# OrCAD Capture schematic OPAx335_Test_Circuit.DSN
size A; title: 0.05µV/°C max, SINGLE-SUPPLY CMOS OPERATIONAL; rev: 1.5; note: Datasheet: SBOS245D  EVM: N/A
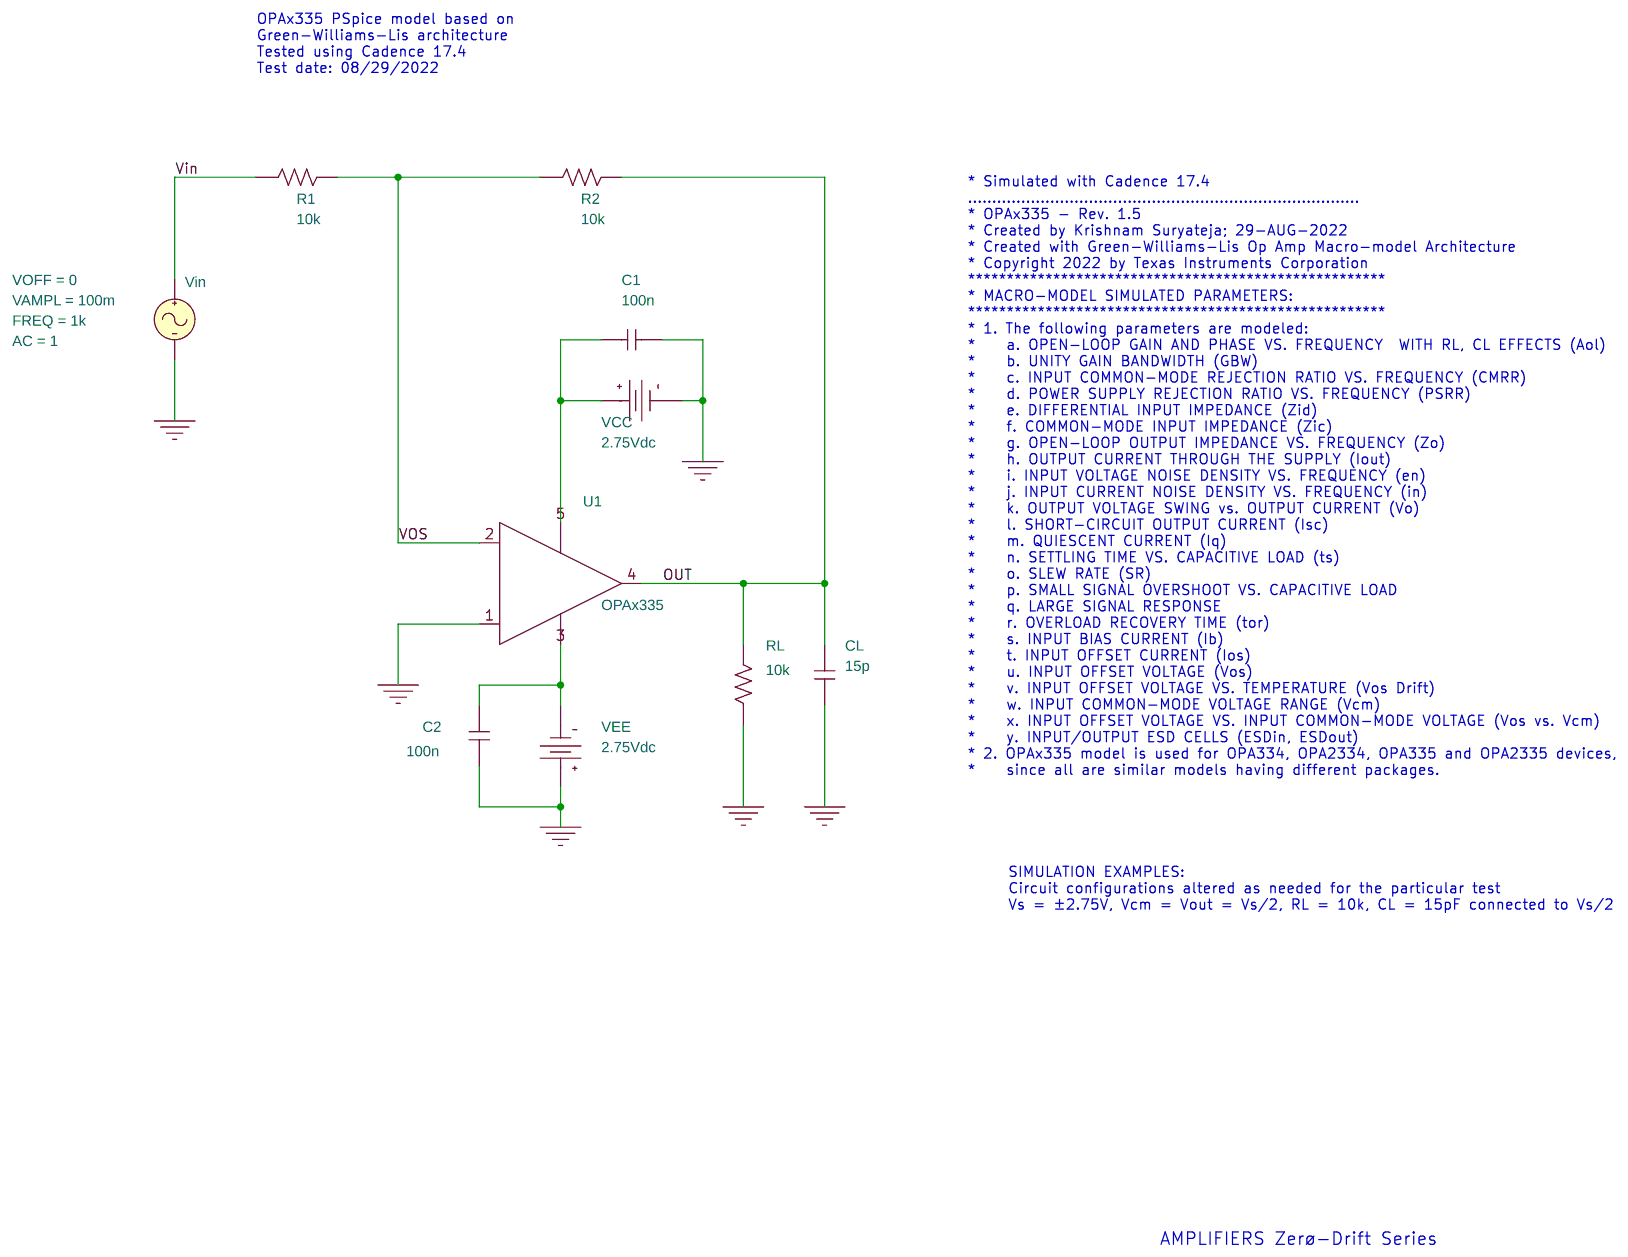
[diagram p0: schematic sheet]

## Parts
C1  100n  [cap196]
C2  100n  [cap196]
CL  15p  [RAD/CK05]
R1  10k  [AXRC05]
R2  10k  [AXRC05]
RL  10k  [AXRC05]
U1  OPAx335
VCC  VDC
VEE  VDC
Vin  VSIN

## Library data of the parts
C1 C2 CL = C
R1 R2 RL = R
U1 = OPAx335
VCC VEE = VDC: DC: 2.75Vdc
Vin = VSIN: AC: 1; FREQ: 1k; VAMPL: 100m; VOFF: 0

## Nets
Vin: R1.1 Vin.1(+)
0: C1.2 C2.1 CL.1 RL.1 U1.1(+) VCC.1(-) VEE.0(+) Vin.2(-)
OUT: CL.2 R2.2 RL.2 U1.4(OUT)
VOS: R1.2 R2.1 U1.2(-)
N27303: C1.1 U1.5(V+) VCC.0(+)
N27354: C2.2 U1.3(V-) VEE.1(-)

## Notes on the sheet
- OPAx335 PSpice model based on
  Green-Williams-Lis architecture
  Tested using Cadence 17.4
  Test date: 08/29/2022
- * Simulated with Cadence 17.4
  .................................................................................
  * OPAx335 - Rev. 1.5
  * Created by Krishnam Suryateja; 29-AUG-2022
  * Created with Green-Williams-Lis Op Amp Macro-model Architecture
  * Copyright 2022 by Texas Instruments Corporation
  ******************************************************
  * MACRO-MODEL SIMULATED PARAMETERS:
  ******************************************************
  * 1. The following parameters are modeled:
  *    a. OPEN-LOOP GAIN AND PHASE VS. FREQUENCY  WITH RL, CL EFFECTS (Aol)
  *    b. UNITY GAIN BANDWIDTH (GBW)
  *    c. INPUT COMMON-MODE REJECTION RATIO VS. FREQUENCY (CMRR)
  *    d. POWER SUPPLY REJECTION RATIO VS. FREQUENCY (PSRR)
  *    e. DIFFERENTIAL INPUT IMPEDANCE (Zid)
  *    f. COMMON-MODE INPUT IMPEDANCE (Zic)
  *    g. OPEN-LOOP OUTPUT IMPEDANCE VS. FREQUENCY (Zo)
  *    h. OUTPUT CURRENT THROUGH THE SUPPLY (Iout)
  *    i. INPUT VOLTAGE NOISE DENSITY VS. FREQUENCY (en)
  *    j. INPUT CURRENT NOISE DENSITY VS. FREQUENCY (in)
  *    k. OUTPUT VOLTAGE SWING vs. OUTPUT CURRENT (Vo)
  *    l. SHORT-CIRCUIT OUTPUT CURRENT (Isc)
  *    m. QUIESCENT CURRENT (Iq)
  *    n. SETTLING TIME VS. CAPACITIVE LOAD (ts)
  *    o. SLEW RATE (SR)
  *    p. SMALL SIGNAL OVERSHOOT VS. CAPACITIVE LOAD
  *    q. LARGE SIGNAL RESPONSE
  *    r. OVERLOAD RECOVERY TIME (tor)
  *    s. INPUT BIAS CURRENT (Ib)
  *    t. INPUT OFFSET CURRENT (Ios)
  *    u. INPUT OFFSET VOLTAGE (Vos)
  *    v. INPUT OFFSET VOLTAGE VS. TEMPERATURE (Vos Drift)
  *    w. INPUT COMMON-MODE VOLTAGE RANGE (Vcm)
  *    x. INPUT OFFSET VOLTAGE VS. INPUT COMMON-MODE VOLTAGE (Vos vs. Vcm)
  *    y. INPUT/OUTPUT ESD CELLS (ESDin, ESDout)
  * 2. OPAx335 model is used for OPA334, OPA2334, OPA335 and OPA2335 devices,
  *    since all are similar models having different packages.
- SIMULATION EXAMPLES:
  Circuit configurations altered as needed for the particular test
  Vs = ±2.75V, Vcm = Vout = Vs/2, RL = 10k, CL = 15pF connected to Vs/2
- AMPLIFIERS Zerø-Drift Series
